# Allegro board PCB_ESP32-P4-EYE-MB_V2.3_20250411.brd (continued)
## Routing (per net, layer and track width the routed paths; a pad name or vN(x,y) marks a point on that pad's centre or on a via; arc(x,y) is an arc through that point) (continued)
C6_U0TXD: length 34.4
  TOP w0.127: U11.31 v1(33.58,30.9) ; R250.2 28.02,12.43 v1(27.97,12.38)
  BOTTOM w0.127: v1(27.97,12.38) 27.7,12.65 23.95,12.65 21.96,14.64 21.96,20.41 21.64,20.73 21.64,22.5 21.96,22.82 21.96,25.03 24.04,27.11 29.65,27.11 33.44,30.9 v1(33.58,30.9) 33.58,31.4 TP47.1
CAM_3V3: length 28.9
  TOP w0.3: J24.23 39.25,33.74 39,33.99 38.75,33.73 J24.24
  TOP w0.381: v1(38.21,34.45) C47.1 39,34.17 39,33.99
  L5_POWER w0.381: v1(54.19,26.29) v1(56.78,26.29)
  BOTTOM w0.381: U16.5 C141.1 TP51.1 57.61,26.29 v1(56.78,26.29) ; v1(54.19,26.29) 52.11,26.29 47.55,30.85 42.43,30.85 38.83,34.45 v1(38.21,34.45)
CAM_CN: length 2.1
  TOP w0.089: R25.1 46.87,34.76 46.87,34.5 C164.1 46.87,34.16 46.87,33.98 46.75,33.86 J24.8
CAM_CP: length 2.1
  TOP w0.089: J24.7 47.25,33.86 47.13,33.98 47.13,34.15 47.3,34.33 47.13,34.5 47.13,34.77 R24.1
CAM_DN: length 2.1
  TOP w0.089: J24.19 41.25,33.77 41.13,33.89 41.13,34.17 C165.1 41.11,34.5 41.11,34.76 R27.1
CAM_DP: length 2.1
  TOP w0.089: R26.1 40.85,34.76 40.85,34.5 C166.1 40.87,34.14 40.87,33.88 40.75,33.77 J24.20
CAM_I2C_SCL: length 6.5
  TOP w0.127: v1(50.32,30.72) 49.25,31.79 J24.3
  BOTTOM w0.127: R303.1 53.95,30.72 v1(50.32,30.72)
CAM_I2C_SDA: length 7.2
  TOP w0.127: v1(50.23,31.42) 49.75,31.9 J24.2
  BOTTOM w0.127: R302.1 50.34,30.06 49.92,30.48 49.92,31.11 v1(50.23,31.42)
CAM_MCLK: length 1.6
  TOP w0.127: J24.5 48.25,34.11 R304.2
CAM_RESET: length 23.2
  TOP w0.127: v1(39.57,32.16) 39.75,32.33 J24.22 39.75,34.07 R67.2 ; v1(29.82,17.07) 29.87,17.02 U4.55
  L5_POWER w0.127: v1(29.82,17.07) 31.47,18.72 33.46,18.72 39.45,24.7 39.45,32.03 v1(39.57,32.16)
CNN_GPIO6: length 20.7
  TOP w0.127: U4.6 48.55,10.72 53.42,15.58 53.42,18.01 53.73,18.33 53.73,19.2 54.3,19.77 J22.9
CNN_GPIO7: length 26.6
  TOP w0.127: J22.8 58.73,22.31 57.44,21.02 54.18,21.02 53.43,20.27 53.43,18.5 53.11,18.19 53.11,15.74 48.44,11.07 U4.7
CNN_GPIO8: length 22.5
  TOP w0.127: U4.8 40.67,11.42 40.74,11.34 48.23,11.34 52.29,15.39 52.29,17.82 53.1,18.63 53.1,21.11 54.3,22.31 J22.7
CNN_GPIO10: length 24.4
  TOP w0.127: U4.11 40.58,12.47 40.75,12.29 41.71,12.29 42.08,11.93 47.88,11.93 50.86,14.91 50.86,21.21 53.86,24.21 53.86,24.4 54.31,24.85 J22.5
CNN_GPIO34: length 61.6
  TOP w0.127: U4.65 29.61,13.52 29.34,13.79 28.18,13.79 v1(28.07,13.68) ; v1(41.5,11.9) 41.77,11.63 48.06,11.63 51.46,15.04 51.46,21.29 53.9,23.72 57.59,23.72 58.72,24.85 J22.6
  L3_SIGNAL w0.127: v1(41.5,11.9) 42.99,11.9 44.11,13.02 44.11,13.39 43.85,13.64 43.85,19.98 42.67,21.16 39.71,21.16 37.15,18.59 34.73,18.59 34.16,18.02 32.26,18.02 31.95,17.72 31.95,14.24 31.33,13.61 28.13,13.61 v1(28.07,13.68)
CNN_GPIO37: length 51.2
  TOP w0.127: R259.2 26.43,11.67 23.94,9.18 23.94,1.31 24.38,0.86 32.42,0.86 32.6,0.69 48.72,0.69 54.19,6.16 56.88,6.16 57.79,7.07 J22.20
CNN_GPIO38: length 47.2
  TOP w0.127: J22.19 54.2,7.07 53.86,6.73 53.86,6.4 48.4,0.94 32.83,0.94 32.65,1.12 24.54,1.12 24.21,1.45 24.21,9.06 26.44,11.29 28.34,11.29 R118.2
CNN_GPIO50: length 35
  TOP w0.127: U4.93 35.84,7.55 34.9,6.62 34.9,2.97 36.39,1.49 47.79,1.49 53.53,7.23 53.53,7.82 54.06,8.36 57.49,8.36 58.75,9.61 J22.18
CNN_GPIO51: length 30.2
  TOP w0.127: J22.17 54.29,9.61 53.25,8.57 53.25,7.42 47.68,1.84 36.59,1.84 35.15,3.28 35.15,6.5 36.19,7.54 U4.94
CNN_GPIO52: length 35.8
  TOP w0.127: J22.16 58.76,12.15 57.54,10.93 53.85,10.93 52.95,10.03 52.95,7.57 47.57,2.2 36.74,2.2 35.41,3.53 35.41,6.39 36.54,7.52 U4.95
CNN_GPIO53: length 31
  TOP w0.127: J22.15 54.31,12.15 52.64,10.48 52.64,7.73 47.49,2.58 36.83,2.58 35.66,3.75 35.66,6.27 37.24,7.85 U4.97
CNN_GPIO54: length 32.7
  TOP w0.127: J22.13 54.3,14.69 52.34,12.73 52.34,7.9 47.35,2.91 36.97,2.91 35.92,3.96 35.92,6.16 37.59,7.83 U4.98
CSI_CLKN: length 25.4
  TOP w0.089: R283.2 33.04,20.3 33.04,20.4 v1(32.88,20.56) ; v1(46.7,35.93) 46.86,35.77 46.86,35.64 R25.2
  L3_SIGNAL w0.089: v1(32.88,20.56) 33.04,20.72 33.04,20.97 33.48,21.4 35.5,21.4 36.21,22.11 36.21,26.12 39.35,29.26 42.42,29.26 46.87,33.72 46.87,35.76 v1(46.7,35.93)
CSI_CLKN_A: length 1.6
  TOP w0.089: R283.1 33.03,19.41 33.03,19.18 33.43,18.78 33.43,18.65 33.39,18.61 U4.45
CSI_CLKP: length 25.4
  TOP w0.089: v1(33.46,20.56) 33.3,20.4 33.3,20.27 R284.2 ; v1(47.29,35.93) 47.13,35.76 47.13,35.64 R24.2
  L3_SIGNAL w0.089: v1(33.46,20.56) 33.3,20.72 33.3,20.86 33.58,21.14 35.6,21.14 36.46,22 36.46,26.01 39.46,29 42.52,29 47.13,33.61 47.13,35.77 v1(47.29,35.93)
CSI_CLKP_A: length 1.6
  TOP w0.089: R284.1 33.29,19.41 33.29,19.29 33.69,18.88 33.69,18.66 33.74,18.61 U4.44
CSI_DATA0N: length 25.1
  TOP w0.089: R286.2 35.01,20.29 35.01,22.15 v1(35.17,22.31) ; v1(41.29,35.97) 41.13,35.81 41.13,35.64 R27.2
  L3_SIGNAL w0.089: v1(41.29,35.97) 41.12,35.81 41.12,32.11 39.32,30.3 39.01,30.3 38.56,29.85 38.2,29.85 37.65,30.41 37.5,30.41 37.4,30.3 37.4,30.15 37.95,29.6 37.95,29.24 37.7,28.98 37.34,28.98 36.78,29.54 36.63,29.54 36.53,29.44 36.53,29.29 37.09,28.73 37.09,28.37 36.83,28.12 36.47,28.12 35.92,28.67 35.77,28.67 35.66,28.57 35.66,28.42 36.22,27.87 36.22,27.51 35.28,26.57 35.28,23.18 35.01,22.9 35.01,22.48 v1(35.17,22.31)
CSI_DATA0N_A: length 1.8
  TOP w0.089: R286.1 35.01,19.42 35.01,19.18 34.73,18.9 34.53,18.9 34.39,18.76 34.39,18.65 34.44,18.61 U4.42
CSI_DATA0P: length 25.1
  TOP w0.089: v1(40.7,35.97) 40.86,35.81 40.86,35.66 R26.2 ; R285.2 34.75,20.29 34.75,22.15 v1(34.59,22.31)
  L3_SIGNAL w0.089: v1(40.7,35.97) 40.87,35.81 40.87,32.21 39.21,30.56 38.91,30.56 38.46,30.11 38.31,30.11 37.75,30.66 37.39,30.66 37.14,30.41 37.14,30.05 37.7,29.49 37.7,29.35 37.59,29.24 37.44,29.24 36.89,29.8 36.53,29.8 36.27,29.54 36.27,29.18 36.83,28.63 36.83,28.48 36.72,28.38 36.58,28.38 36.02,28.93 35.66,28.93 35.41,28.68 35.41,28.32 35.96,27.76 35.96,27.61 35.02,26.67 35.02,23.28 34.75,23.01 34.75,22.48 v1(34.59,22.31)
CSI_DATA0P_A: length 1.8
  TOP w0.089: R285.1 34.75,19.41 34.75,19.29 34.63,19.16 34.42,19.16 34.13,18.87 34.13,18.65 34.09,18.61 U4.43
CSI_REXT: length 1.5
  TOP w0.18: U4.48 32.34,19.19 R203.1
DSI_REXT: length 0.9
  TOP w0.18: R202.1 37.24,19.06 U4.34
EN_DCDC: length 5.3
  TOP w0.127: v1(28.32,5.91) 28.32,6.88 29.41,7.98 30.7,7.98 30.94,8.22 U4.79
  BOTTOM w0.127: v1(28.32,5.91) 28.32,5.78 28.32,5.78 U1.1
ENCODER_A: length 46.4
  TOP w0.127: v1(34.79,7.44) U4.90 ; R292.1 23.01,10.38 v1(22.17,9.53) 21.15,9.53 20.18,10.5 20.18,13.7 19.56,14.33 18.26,14.33 16.89,15.7 16.89,20.55 15.98,21.46 10.68,21.46 7.94,24.21 7.94,24.81 SW6.1
  L3_SIGNAL w0.127: v1(34.79,7.44) 34.7,7.53 33.93,7.53 32.16,5.75 29.24,5.75 28.65,6.34 24.46,6.34 23.94,6.86 23.94,7.94 22.35,9.53 v1(22.17,9.53)
ENCODER_B: length 36.9
  TOP w0.127: SW6.4 15.62,25.15 18.05,22.72 18.05,16.76 21.76,13.06 22.23,13.06 R293.1 21.35,11.88 v1(21.35,10.35) ; v1(34.4,7.07) 34.37,7.11 34.37,7.86 34.44,7.93 U4.89
  L3_SIGNAL w0.127: v1(21.35,10.35) 21.35,9.66 21.91,9.11 22.36,9.11 23.6,7.87 23.6,6.34 24.51,5.42 32.26,5.42 32.75,5.92 33.45,5.92 34.4,6.86 v1(34.4,7.07)
ENCODER_SW: length 47.7
  TOP w0.127: v1(40.97,8.81) 40.97,9 40.66,9.32 U4.2 ; SW6.2 10.12,23.81 R295.1 10.93,23.81 12.45,22.29 16.24,22.29 17.49,21.04 17.49,16.14 v1(18.62,15.01)
  L3_SIGNAL w0.127: v1(18.62,15.01) 18.48,14.86 18.48,13.36 19.18,12.66 19.94,12.66 21.44,11.16 21.44,10.87 24.27,8.04 24.27,6.95 24.63,6.59 28.77,6.59 29.31,6.05 32.07,6.05 33.86,7.84 38.48,7.84 39.14,7.18 39.74,7.18 40.14,7.58 40.14,8.46 40.5,8.81 v1(40.97,8.81)
ESP_3V3: length 187.8
  TOP w0.18: 38.62,8.78 38.64,8.76 U4.101 ; U4.51 31.29,17.86 ; 39.75,15.97 U4.21 ; U4.62 30.8,14.57 v1(31.04,14.33) ; U4.75 v1(30.99,10.02) ; v1(31,9.32) U4.77 ; 38.99,8.79 U4.102 ; v1(39.59,11.77) U4.9 ; 36.89,8.78 U4.96
  TOP w0.2: v1(31.29,23.5) 31.1,23.69 R135.2 ; R4.2 R3.1 26.53,12.43 v1(26.02,11.93)
  TOP w0.254: v1(36.89,9.08) 36.89,8.78 ; v1(39.13,9.09) 38.99,8.95 38.99,8.79 ; C110.1 21.07,32.45 R134.2 ; 38.62,8.78 38.62,8.9 v1(38.46,9.07) ; v1(10.74,23.03) 10.46,23.31 R295.2 ; 31.29,17.86 31.29,17.72 v1(31.37,17.64)
  TOP w0.381: v1(39.45,15.97) 39.75,15.97
  TOP w0.635: C109.1 C110.1 21.17,32.46 22.46,32.46 U11.3
  L3_SIGNAL w0.254: v1(22.03,7.33) 21.16,6.45 v1(21.16,1.89)
  L5_POWER w0.2: 20.22,11.98 20.16,11.92 v1(19.47,11.92) ; v1(26.02,11.93) 26.02,11.76 25.49,11.23 ; 51.67,20.5 51.71,20.46 52.27,20.46 v1(52.4,20.33) ; 19.65,25.36 13.08,25.36 v1(10.74,23.03) ; v1(20.08,18.87) 20.33,18.87
  L5_POWER w0.508: 52.13,20.97 52.4,20.7 v1(52.4,20.33) ; v1(36.61,20.56) 38.07,19.11 38.07,15.92
  L5_POWER w0.762: 21.22,2.18 21.22,6.63 20.22,7.63 20.22,11.98 20.74,12.5 20.74,17.49 20.33,17.89 20.33,23.9 v1(19.81,24.42) 19.65,24.59 v1(19.65,32.07) ; 40.16,10.9 46.35,10.9 50.11,14.66 50.11,18.95 52.13,20.97 63.18,20.97 67.13,24.92 67.13,31.41 66.93,31.61
  L5_POWER w1.2: v1(21.16,1.89) 21.31,1.74 22.21,1.74 23.65,3.17 23.65,9.39 25.49,11.23 28.17,11.23 29.58,12.64 29.58,12.92 30.58,13.92 31.29,13.92
  BOTTOM w0.2: R263.2 19.96,18.76 v1(20.08,18.87) ; 33.77,24.57 33.77,25.43 R133.1 34.25,25.45 34.54,25.74 R132.1 R131.1 R130.1 R129.1 R128.1 ; 33.77,24.57 34.34,24 34.92,24 36.2,22.73 36.2,21.4 Q8.2 ; 33.77,24.57 32.11,24.57 31.29,23.76 v1(31.29,23.5) ; R262.2 19.88,24.36 v1(19.81,24.42) ; v1(52.4,20.33) 52.69,20.04 53.12,20.04 R306.1 ; v1(36.61,20.56) 36.61,20.41 R309.2 ; R2.2 39.89,9.59 C82.1 ; C174.1 64.39,34.08 R230.2 ; v1(19.47,11.92) R264.2
  BOTTOM w0.254: R146.1 C121.1 21.79,7.33 v1(22.03,7.33)
  BOTTOM w0.381: C90.1 36.89,9.59 v1(36.89,9.08) ; v1(31,9.32) 31.14,9.18 C96.1 C95.1 ; C88.1 39.35,16.06 v1(39.45,15.97) ; C87.1 39.31,11.49 v1(39.59,11.77) 39.87,11.49 C83.1 ; C85.1 38.07,9.45 v1(38.46,9.07) ; C82.1 C84.1 39.13,9.42 v1(39.13,9.09) ; TP53.1 27.47,32.42 19.82,32.42 v1(19.65,32.6) ; v1(30.99,10.02) 30.98,10.02 30.78,10.21 C103.1 ; v1(31.04,14.33) 31.05,14.31 C97.1 ; v1(52.4,20.33) 52.45,20.39 Q2.2 ; v1(31.14,14.86) 31.29,14.86 31.77,15.34 C98.1 C99.1 C100.1 31.84,17.17 v1(31.37,17.64)
  BOTTOM w0.508: v1(36.61,20.56) 36.12,21.05 Q8.2
  BOTTOM w0.635: TP49.1 21.58,2.64 22.59,3.66 22.59,5.72 24.69,7.82 C6.1 26.19,7.82 U1.4
  BOTTOM w0.762: Q10.2 63.08,33.14 63.58,32.63 C174.1 C178.1 v1(67.01,32.63)
  BOTTOM w1.2: 19.95,1.62 L5.2
  vias: v1(20.59,1.9) v1(20.61,1.34) v1(21.16,1.33) v1(67.01,32.06)
ESP_EN: length 49.1
  TOP w0.127: v1(19.2,13.64) 17.4,13.64 10.15,20.89 4.41,20.89 2.63,22.67 2.63,23 1.05,24.58 SW1.3 ; U4.103 39.34,7.93 v1(39.42,7.85)
  L3_SIGNAL w0.127: v1(39.42,7.85) 38.89,8.38 32.85,8.38 31.33,6.86 29.69,6.86 29.16,7.39 25.68,7.39 22.05,11.02 22.05,11.62 20.03,13.64 v1(19.2,13.64)
  BOTTOM w0.127: R2.1 39.51,7.85 v1(39.42,7.85) 39.42,7.85 C2.2
ESP_I2C_SCL: length 42.8
  TOP w0.127: U4.14 41.17,13.52 v1(41.24,13.45) ; J22.12 58.03,17.23 v1(57.32,17.95)
  L3_SIGNAL w0.127: v1(57.33,28.94) 56.67,28.94 55.5,27.77 55.5,18.66 56.03,18.12 57.14,18.12 v1(57.32,17.95)
  BOTTOM w0.127: v1(41.24,13.45) 41.33,13.36 41.76,13.36 42.66,12.46 50.25,12.46 54.94,17.14 56.52,17.14 v1(57.32,17.95) 57.51,17.95 58.28,18.72 58.28,20.03 58.01,20.3 U13.12 ; v1(57.33,28.94) 56.91,28.94 55.14,30.71 R273.1 54.47,30.71 R303.2
ESP_I2C_SDA: length 39.6
  TOP w0.127: J22.10 57.93,19.77 57.44,19.28 v1(57.44,18.47) ; v1(41.66,13.78) 41.57,13.87 U4.15
  L3_SIGNAL w0.127: v1(56.83,28.54) 55.83,27.53 55.83,18.83 56.2,18.47 v1(57.44,18.47)
  BOTTOM w0.127: U13.2 57.39,18.52 v1(57.44,18.47) 57.25,18.47 56.27,17.49 54.7,17.49 49.93,12.71 42.77,12.71 41.71,13.78 v1(41.66,13.78) ; R302.2 54.47,30.06 R272.1 55.31,30.06 v1(56.83,28.54)
ESP_LDO_VO1: length 34.3
  TOP w0.18: v1(30.99,11.45) 30.96,11.42 U4.71 ; 38.64,18.79 U4.30
  TOP w0.2: v1(43.03,13.41) 42.75,13.69 42.75,13.86 R7.2
  TOP w0.254: 38.64,18.79 40.09,20.24 40.37,20.24 C25.1 C20.1 42.41,20.37 v1(42.55,20.23)
  TOP w0.381: U2.8 43.37,20.2 C5.1 42.68,20.37 v1(42.55,20.23)
  L3_SIGNAL w0.2: v1(42.55,20.23) 43.27,19.51 43.27,15.67 42.62,15.02 42.62,13.82 v1(43.03,13.41)
  L3_SIGNAL w0.381: v1(30.99,11.45) 33.04,11.45 34.57,12.98 34.57,14.88 35.89,16.21 36.84,16.21 41.02,20.38 42.39,20.38 v1(42.55,20.23)
  BOTTOM w0.254: C56.1 30.03,12.02 TP26.1
  BOTTOM w0.381: v1(30.99,11.45) 30.82,11.62 C56.1
ESP_LDO_VO2: length 11.5
  TOP w0.18: v1(30.98,15.72) 30.87,15.62 U4.59 ; v1(30.95,12.89) 30.88,12.82 U4.67 ; 29.88,10.93 30.02,11.07 U4.72
  TOP w0.254: 29.88,10.93 29.77,10.82 v1(29.71,10.82) 29.64,10.75 C50.1
  BOTTOM w0.254: v1(29.71,10.82) TP24.1 28.71,11.02 28.71,12.74 29.97,14 ; 30.11,14.14 30.11,14.12 30.24,14 ; 30.11,14.14 29.97,14 ; 30.11,14.14 30.11,15.3 C105.1 30.88,15.63 v1(30.98,15.72) ; 29.97,14 30.24,14 ; 30.24,14 30.84,13.39 C104.1 v1(30.95,12.89)
ESP_LDO_VO3: length 10.8
  TOP w0.18: U4.41 v1(34.79,17.69) ; v1(30.98,10.72) U4.73
  BOTTOM w0.254: v1(34.79,17.69) 34.57,17.48 C93.1 C92.1 C91.1 34.57,13.43 TP27.1 33.17,11.56 32.19,11.56 31.68,11.04 C55.1 31.56,10.85 31.1,10.85 v1(30.98,10.72)
ESP_LDO_VO4: length 56.3
  TOP w0.18: 30.05,10.37 U4.74 ; 33.04,7.94 U4.85
  TOP w0.2: v1(49.1,25.04) 49.1,25.18 ; 49.1,25.18 47.18,25.18 ; 49.1,25.18 50.75,25.18 v1(50.89,25.04) ; v1(38.27,25.01) v1(40.31,25.01) 40.48,25.18 47.18,25.18 ; R293.2 R292.2 23.45,13.41 v1(24.02,13.97) ; 47.18,25.18 v1(47.18,25.04)
  TOP w0.254: v1(29.73,10.24) 29.86,10.37 30.05,10.37 ; 33.04,7.94 33.04,7.57 32.98,7.52
  TOP w0.381: v1(29.73,10.24) 29.67,10.24 29.28,9.85 C51.1 ; v1(32.82,7.36) 32.98,7.52
  L3_SIGNAL w0.254: v1(24.02,13.97) 25.29,12.7 26.38,12.7 28.84,10.24 v1(29.73,10.24)
  L5_POWER w0.254: v1(38.27,25.01) 38.07,25.01 37.35,24.28 35.06,24.28 32.28,21.49 30.91,21.49 29.07,19.66 29.07,16.41 28.61,15.95 28.61,15.09 28.04,14.52 27.75,14.52 26.95,13.72 24.27,13.72 v1(24.02,13.97)
  L5_POWER w0.3: v1(32.82,7.36) 31.65,7.36 30.21,8.8 30.21,9.75 v1(29.73,10.24)
  BOTTOM w0.2: R17.1 47.25,25.11 v1(47.18,25.04) ; R231.1 49.06,25.08 v1(49.1,25.04) ; v1(40.31,25.01) 40.31,25.01 R232.1 ; R280.1 R233.1 38.45,25.26 38.27,25.07 v1(38.27,25.01) ; R234.1 v1(50.89,25.04)
  BOTTOM w0.381: v1(32.82,7.36) 32.82,7 C101.1 C102.1 32.51,5.71 TP25.1
ESP_VDD_HP: length 40.7
  TOP w0.18: 30.03,9.67 U4.76 ; U4.26 39.72,17.72 v1(39.54,17.54) ; 35.14,8.84 U4.91
  TOP w0.254: v1(29.29,1.98) 28.3,2.97 28.3,4.41 25.97,6.73 v1(25.97,9.65) ; v1(35.15,9.07) 35.14,9.05 35.14,8.84 ; v1(29.72,9.42) 29.97,9.67 30.03,9.67
  BOTTOM w0.254: R8.1 26.51,9.65 C7.1 v1(25.97,9.65)
  BOTTOM w0.381: v1(39.54,17.54) 39.16,17.92 C86.1 38.62,17.46 37.16,16 37.16,12.19 35.26,10.29 35.26,9.17 v1(35.15,9.07) ; 30.69,8.15 30.69,8.16 30.01,8.84 C107.1 29.81,9.33 v1(29.72,9.42)
  BOTTOM w0.508: v1(35.15,9.07) 35.08,9 C94.1 34.64,8.91 33.96,8.23 30.77,8.23 30.69,8.15
  BOTTOM w0.635: 30.69,8.15 C89.1 30.69,6.65 29.83,5.79 29.83,2.53 v1(29.29,1.98) C173.1 C8.1 27.85,1.98 L1.2
FB_DCDC: length 5.2
  TOP w0.18: 29.99,8.97 U4.78
  TOP w0.254: v1(28.83,8.88) 28.93,8.78 29.79,8.78 29.99,8.97
  BOTTOM w0.254: R9.1 28.32,8.79 U1.5 ; R9.1 R8.2 26.51,8.79 C7.2 ; R9.1 28.74,8.79 v1(28.83,8.88)
FLASH_CK: length 12.4
  TOP w0.127: U2.6 47.05,20.4 45.91,21.54 42.65,21.54 42.16,22.02 40.2,22.02 37.94,19.76 U4.32
FLASH_CS: length 10.1
  TOP w0.127: v1(44.54,13.97) 44.51,14 U2.1 ; R7.1 43.2,14.36 v1(43.15,14.4) 43.27,14.52 43.27,17.53 42.3,18.49 39.78,18.49 39.69,18.4 U4.27
  L5_POWER w0.127: v1(44.54,13.97) 44.11,14.4 v1(43.15,14.4)
FLASH_D: length 14.3
  TOP w0.127: U4.33 37.59,19.78 40.09,22.29 42.28,22.29 42.76,21.81 46.92,21.81 48.32,20.41 U2.5
FLASH_HD: length 10.4
  TOP w0.127: U2.7 45.78,20.83 45.43,21.18 39.72,21.18 38.23,19.69 38.23,18.75 38.29,18.68 U4.31
FLASH_Q: length 11.6
  TOP w0.127: U2.2 45.78,14.47 44.87,13.56 44.27,13.56 43.6,14.24 43.6,17.6 42.41,18.78 39.55,18.78 39.34,18.57 U4.28
FLASH_WP: length 11.7
  TOP w0.127: U4.29 38.99,18.59 39.44,19.04 42.56,19.04 43.89,17.7 43.89,15.7 44.17,15.42 46.53,15.42 47.05,14.9 U2.3
GPIO0: length 2.3
  TOP w0.127: R61.1 41.12,7.67 40.28,7.67 39.69,8.27 U4.104
GPIO1: length 1.9
  TOP w0.127: U4.1 40.45,8.97 40.58,8.84 40.58,8.22 40.77,8.02 R59.1
GPIO11: length 34.7
  TOP w0.127: R304.1 51.44,34.57 53.21,32.79 53.21,24.73 49.57,21.08 49.57,14.62 47.68,12.73 41.92,12.73 41.74,12.55 40.87,12.55 40.6,12.82 U4.12
GPIO21: length 1.1
  TOP w0.127: U4.23 40.58,16.67 40.67,16.75 41.03,16.75 R255.1
GPIO22: length 1.2
  TOP w0.127: U4.24 40.66,17.02 R23.1
GPIO24: length 2.2
  TOP w0.114: R104.1 29.19,18.36 30.22,18.36 30.41,18.55 30.81,18.55 30.94,18.43 U4.52
GPIO25: length 1.7
  TOP w0.114: R105.1 29.05,17.96 29.17,18.07 29.96,18.07 30.07,17.96 30.07,17.83 30.19,17.72 U4.53
GPIO27: length 1.9
  TOP w0.114: U4.56 29.61,16.67 29.27,17.01 R278.1
GPIO28: length 1.8
  TOP w0.114: U4.57 29.47,16.32 29.43,16.36 R277.1
GPIO29: length 3
  TOP w0.114: R276.1 28.77,15.81 28.92,15.97 U4.58
GPIO30: length 1.8
  TOP w0.114: R275.1 28.65,15.16 29.76,15.16 29.86,15.27 U4.60
GPIO31: length 3
  TOP w0.114: R274.1 27.53,14.81 29.83,14.81 29.94,14.92 U4.61
GPIO32: length 1.9
  TOP w0.114: U4.63 30,14.22 29.77,14.45 28.65,14.45 R279.1
GPIO35_BOOT: length 44.1
  TOP w0.127: SW2.3 1.05,32.04 2.11,33.1 13.35,33.1 18.87,27.57 18.87,18.81 19.63,18.05 20.89,18.05 25.49,13.45 25.49,13.27 C3.1 R4.1 26.44,13.15 26.78,13.5 27.69,13.5 27.9,13.28 28.24,13.28 28.49,13.53 28.93,13.53 29.22,13.24 R300.1 29.23,13.17 U4.66
GPIO36: length 3.3
  TOP w0.127: U4.68 29.25,12.47 R250.1 29.22,12.51 28.96,12.78 27.78,12.78 R3.2
GPIO37: length 2.5
  TOP w0.127: R259.1 28.42,12.05 29.86,12.05 29.92,12.12 U4.69
GPIO38: length 1.2
  TOP w0.127: R118.1 29.31,11.77 U4.70
GPIO39: length 2.6
  TOP w0.114: R122.1 29.66,6.74 30.54,7.62 30.82,7.62 31.29,8.09 U4.80
GPIO40: length 2.3
  TOP w0.114: R110.1 30.84,7.32 30.94,7.32 31.64,8.02 U4.81
GPIO41: length 2.1
  TOP w0.114: R108.1 31,6.83 31,6.99 31.99,7.97 U4.82
GPIO42: length 2
  TOP w0.114: U4.83 32.34,7.89 31.56,7.11 R107.1
GPIO43: length 1.9
  TOP w0.114: U4.84 32.69,7.82 32.19,7.33 R103.1
GPIO44: length 1.9
  TOP w0.114: R102.1 33.4,7.31 33.4,8.4 U4.86
LCD_BL: length 21.4
  TOP w0.127: v1(40.78,16.32) 40.78,16.32 U4.22
  BOTTOM w0.127: Q2.1 54.35,19.91 R79.1 R306.2 53.76,18.33 49.77,14.35 45.92,14.35 44.87,13.3 44.16,13.3 43.62,13.83 42.91,13.83 42.25,14.49 41.07,14.49 40.46,15.1 40.46,16 v1(40.78,16.32)
LCD_CS: length 11.8
  TOP w0.127: U4.19 41.1,15.27 v1(41.16,15.33) 41.26,15.43 41.26,15.73 R241.1
  BOTTOM w0.127: v1(41.16,15.33) 41.16,15.27 41.43,15 42.42,15 44.08,16.66 44.08,21.48 43.75,21.81 J5.8
LCD_DC: length 12.4
  TOP w0.127: v1(40.86,15.77) 40.7,15.62 U4.20
  BOTTOM w0.127: v1(40.86,15.77) 40.77,15.68 40.77,15.16 41.19,14.74 42.53,14.74 44.36,16.57 44.36,21.67 44.25,21.78 J5.7
LCD_RST: length 12
  TOP w0.127: U4.16 41.45,14.22 42.62,15.39 R238.1 42.36,16.32 v1(42.24,16.21)
  BOTTOM w0.127: v1(42.24,16.21) 42.43,16.21 43.23,17.01 43.23,20.93 42.25,21.91 J5.11
LCD_SCLK: length 11
  TOP w0.127: U4.18 41.31,14.92 41.69,15.3 v1(41.69,15.39)
  BOTTOM w0.127: J5.9 43.25,21.82 43.8,21.27 43.8,16.75 42.3,15.25 41.83,15.25 v1(41.69,15.39)
LCD_SDA: length 10.9
  TOP w0.127: U4.17 41.43,14.57 42.16,15.3 v1(42.16,15.67)
  BOTTOM w0.127: v1(42.16,15.67) 42.27,15.67 43.52,16.93 43.52,21.08 42.75,21.85 J5.10
LED_A: length 8.7
  BOTTOM w0.3: J5.3 46.25,22.32 46.44,22.12
  BOTTOM w0.381: 46.44,22.12 48.35,22.12 49.91,23.69 53.14,23.69 Q2.3
LED_CTRL: length 20
  TOP w0.127: v1(40.93,18.06) 40.81,17.94 40.81,17.6 40.57,17.37 U4.25 ; Q4.1 42.6,35.79 42.91,35.48 R73.1 42.91,34.57 v1(42.73,34.39)
  L5_POWER w0.127: v1(42.73,34.39) 42.73,34.29 41.58,33.13 41.58,26.8 41.29,26.5 41.29,25.03 40.93,24.67 v1(40.93,18.06)
LED_K: length 2.5
  BOTTOM w0.3: J5.2 46.75,23.83 46.85,23.93
  BOTTOM w0.381: R243.1 47.02,24.09 46.85,23.93
LPI2S_CLK: length 26.2
  TOP w0.127: v1(42.1,17.7) 41.85,17.7 R23.2 ; 47.6,40.38 47.37,40.38 46.88,39.88 46.88,38.57 v1(45.2,36.89)
  L5_POWER w0.127: v1(42.1,17.7) 42.1,18.8 43.14,19.84 43.14,21.27 43.59,21.72 43.59,23.65 42.99,24.24 42.99,26.12 42.82,26.29 42.82,28.3 42.98,28.45 42.98,31.64 45.2,33.86 v1(45.2,36.89)
LPI2S_DAT: length 30
  TOP w0.127: v1(45.61,36.53) 45.9,36.82 48.95,36.82 49.7,37.57 49.7,39.89 49.21,40.38 U9.4 ; v1(42.19,17.17) 41.95,17.17 R255.2
  L5_POWER w0.127: v1(45.61,36.53) 45.61,33.78 43.29,31.47 43.29,28.78 43.79,28.28 43.79,27.11 43.31,26.63 43.31,24.31 43.89,23.72 43.89,21.6 43.45,21.16 43.45,19.77 42.49,18.82 42.49,17.48 v1(42.19,17.17)
PWR_CTRL: length 37.9
  TOP w0.127: v1(62.98,24.5) 62.32,25.16 62.32,27.79 61.73,28.37 v1(60.31,28.37) ; U4.13 40.81,13.17 v1(41.01,12.97)
  BOTTOM w0.127: R310.2 60.31,27.83 v1(60.31,28.37) Q1.1 ; v1(41.01,12.97) 42.08,11.9 52.84,11.9 62.98,22.03 v1(62.98,24.5) U16.3
SD1_CLK: length 50.6
  TOP w0.114: R103.2 v1(32.19,2.59)
  L3_SIGNAL w0.132: v1(41.92,25.91) 42.09,25.74 42.62,25.74 42.76,25.88 42.76,26.1 42.91,26.25 43.13,26.25 43.29,26.1 43.29,25.88 43.42,25.74 43.85,25.74 45.77,23.82 45.99,23.82 46.17,24 46.39,24 46.54,23.84 46.54,23.62 46.37,23.45 46.37,23.23 50.2,19.39 50.2,8.37 43.83,1.99 33.3,1.99 32.7,2.59 v1(32.19,2.59)
  BOTTOM w0.114: v1(41.92,25.91) D6.2 42.64,25.91 43.01,26.28 43.01,27.24 J21.5
SD1_CMD: length 50.9
  TOP w0.114: R102.2 32.7,6.11 v1(32.7,2.02)
  L3_SIGNAL w0.132: v1(46.88,25.91) 46.88,26.66 47.08,26.86 47.42,26.86 47.6,26.68 47.6,24.17 47.75,24.01 48.64,24.01 48.82,23.84 48.82,23.55 48.67,23.39 48.26,23.39 48.11,23.24 48.11,23.02 48.26,22.86 48.5,22.86 48.63,22.73 48.63,21.59 50.65,19.57 50.65,8.2 44.04,1.6 33.12,1.6 v1(32.7,2.02)
  BOTTOM w0.114: R17.2 46.88,25.91 v1(46.88,25.91) D4.2 46.22,25.91 45.5,26.62 J21.3
SD1_D0: length 50.4
  TOP w0.114: R122.2 29.62,4.64 v1(30.82,3.43)
  L3_SIGNAL w0.132: v1(30.82,3.43) 32.41,3.43 33.45,2.39 43.59,2.39 49.78,8.59 49.78,19.19 43.64,25.34 41.25,25.34 v1(40.68,25.91)
  BOTTOM w0.114: R232.2 40.68,25.91 v1(40.68,25.91) D11.2 41.24,26.25 41.1,26.39 J21.7
SD1_D1: length 50.6
  TOP w0.114: R110.2 30.26,4.58 v1(30.82,4.03)
  L3_SIGNAL w0.132: v1(30.82,4.03) 31.17,4.03 31.27,3.92 31.69,3.92 31.79,4.03 32.36,4.03 33.6,2.78 43.36,2.78 49.34,8.76 49.34,19.05 44.93,23.46 42.39,23.46 41.69,24.16 40.56,24.16 v1(38.82,25.89)
  BOTTOM w0.114: J21.8 40,26.35 39.55,25.89 D10.2 v1(38.82,25.89) 38.82,25.9 R233.2
SD1_D2: length 50.8
  TOP w0.114: R108.2 31.24,5.91 v1(31.24,3)
  L3_SIGNAL w0.132: v1(50.52,25.91) 50.44,25.83 50.44,21.88 51.57,20.75 51.57,18.81 51.8,18.58 51.8,8.12 44.5,0.81 32.68,0.81 31.24,2.25 v1(31.24,3)
  BOTTOM w0.114: R234.2 50.52,25.91 v1(50.52,25.91) D8.2 49.8,25.91 49.14,26.57 48.3,26.57 47.7,27.17 J21.1
SD1_D3: length 50.7
  TOP w0.114: v1(31.66,2.67) 31.66,6.14 R107.2
  L3_SIGNAL w0.132: v1(31.66,2.67) 31.66,2.39 32.84,1.21 44.27,1.21 51.08,8.01 51.08,9.12 51.33,9.37 51.33,9.65 51.08,9.9 51.08,10.17 51.33,10.43 51.33,10.7 51.08,10.96 51.08,11.23 51.33,11.48 51.33,11.76 51.08,12.01 51.08,12.29 51.33,12.54 51.33,12.82 51.08,13.07 51.08,13.34 51.33,13.6 51.33,13.87 51.08,14.13 51.08,14.4 51.33,14.65 51.33,14.93 51.08,15.18 51.08,15.46 51.33,15.71 51.33,15.99 51.08,16.24 51.08,16.51 51.33,16.77 51.33,17.04 51.08,17.3 51.08,17.57 51.33,17.83 51.33,18.1 51.08,18.35 51.08,20.66 49.21,22.53 49.21,24.13 48.69,24.65 v1(48.69,25.91)
  BOTTOM w0.114: J21.2 46.6,27.23 47.92,25.91 D7.2 v1(48.69,25.91) 48.69,25.91 R231.2
SD1_VDD: length 11.6
  BOTTOM w0.381: C149.1 44.24,25.02 D3.2 44.24,26.02 44.4,26.18 J21.4 ; C149.1 44.37,24.66 43.94,24.23 41.11,24.23 40.51,23.63 Q8.3 ; C149.1 C148.1
SD2_CLK: length 15.7
  TOP w0.114: U11.25 v1(33.57,26.1) ; v1(27.69,16.32) 27.72,16.36 R277.2
  BOTTOM w0.114: R132.2 33.57,26.1 v1(33.57,26.1) 33.32,26.35 32.35,26.35 30.18,24.18 30.18,22.52 26.89,19.23 26.89,17.02 27.58,16.32 v1(27.69,16.32)
SD2_CMD: length 14.1
  TOP w0.114: v1(27.6,16.88) 27.72,17.01 R278.2 ; U11.24 33.2,25.78 v1(33.02,25.96)
  BOTTOM w0.114: R133.2 33.29,25.69 v1(33.02,25.96) 32.4,25.96 30.54,24.1 30.54,22.4 27.15,19.01 27.15,17.32 v1(27.6,16.88)
SD2_D0: length 16.1
  TOP w0.114: v1(27.09,16.26) 26.98,16.14 R276.2 ; U11.26 v1(33.58,26.9)
  BOTTOM w0.114: v1(27.09,16.26) 26.61,16.74 26.61,19.38 29.82,22.59 29.82,24.26 32.46,26.9 v1(33.58,26.9) 33.59,26.89 R131.2
SD2_D1: length 18.2
  TOP w0.114: U11.27 v1(33.59,27.7) ; R275.2 27.99,15.33 v1(27.74,15.33)
  BOTTOM w0.114: v1(27.74,15.33) 27.25,15.81 26.87,15.81 26.34,16.34 26.34,19.57 29.46,22.69 29.46,24.37 32.79,27.7 v1(33.59,27.7) 33.59,27.7 R130.2
SD2_D2: length 18.6
  TOP w0.114: R274.2 v1(26.98,15.33) ; U11.28 v1(33.59,28.5)
  BOTTOM w0.114: v1(26.98,15.33) 26.07,16.23 26.07,19.75 29.11,22.78 29.11,24.47 33.14,28.5 v1(33.59,28.5) 33.59,28.5 R129.2
SD2_D3: length 21.2
  TOP w0.114: U11.29 v1(33.59,29.3) ; v1(26.59,14.47) 28.08,14.47 R279.2
  BOTTOM w0.114: R128.2 33.59,29.3 v1(33.59,29.3) 33.45,29.3 28.77,24.61 28.77,22.9 25.81,19.94 25.81,15.25 v1(26.59,14.47)
SD_DET: length 51.8
  TOP w0.127: U4.87 33.74,4.2 v1(33.57,4.03)
  L3_SIGNAL w0.127: v1(48.76,9.73) 48.76,19 44.83,22.92 41.97,22.92 41.17,23.72 38.6,23.72 37.43,24.89 v1(37.43,25.9)
  L5_POWER w0.127: v1(33.57,4.03) 34.11,4.03 35.28,2.86 43.05,2.86 48.76,8.56 v1(48.76,9.73)
  BOTTOM w0.127: R280.2 v1(37.43,25.9) 37.42,25.9 D22.2 36.84,26.2 37.26,26.62 38.33,26.62 38.9,27.19 J21.9
SD_PWRN: length 59.6
  TOP w0.127: v1(38.02,22.12) 39.74,23.84 51.23,23.84 v1(51.9,24.51) ; v1(33.95,3.61) 34,3.66 34,7.92 34.09,8.01 U4.88
  L3_SIGNAL w0.127: v1(52.41,19.35) 53.09,20.03 53.09,23.33 v1(51.9,24.51)
  L5_POWER w0.127: v1(52.41,19.35) 52.29,19.23 52.29,10.16 44.56,2.44 35.12,2.44 v1(33.95,3.61)
  BOTTOM w0.127: v1(38.02,22.12) Q8.1 38.03,21.32 R308.2 R309.1
USB_DM: length 33.1
  TOP w0.114: U4.49 31.95,18.3 31.95,18.81 31.14,19.62 30.85,19.62 v1(30.71,19.76) ; v1(5.05,26.25) v1(5.05,25.26)
  L3_SIGNAL w0.127: v1(8.81,26.2) 8.94,26.07 14.95,26.07 21.4,19.62 30.57,19.62 v1(30.71,19.76)
  BOTTOM w0.114: J6.7 5.07,25.25 v1(5.05,25.26) ; 7.37,26.49 7.42,26.44 7.42,26.19 7.58,26.02 8.63,26.02 v1(8.81,26.2) ; 7.37,26.49 D20.2 ; 7.37,26.49 7.07,26.19 6.54,26.19 6.48,26.25 J6.9 v1(5.05,26.25)
USB_DP: length 35
  TOP w0.114: U4.50 31.66,18.29 31.66,18.69 31.02,19.33 30.88,19.33 v1(30.7,19.15)
  L3_SIGNAL w0.127: v1(8.81,25.59) 8.98,25.76 14.82,25.76 21.27,19.3 30.57,19.3 30.7,19.18 v1(30.7,19.15)
  BOTTOM w0.114: 7.37,25.27 7.1,25.54 7.1,25.78 6.98,25.9 6.67,25.9 6.52,25.75 J6.8 4.15,25.75 3.98,25.92 3.98,26.57 4.16,26.75 J6.10 ; 7.37,25.27 7.43,25.33 7.43,25.62 7.53,25.73 8.7,25.73 8.81,25.61 v1(8.81,25.59) ; 7.37,25.27 D21.2
USB_SJ_DN: length 29.2
  TOP w0.114: v1(28.05,18.49) 28.2,18.34 28.39,18.34 R104.2 ; v1(5.02,11.25) v1(5.02,10.25)
  L3_SIGNAL w0.127: v1(9.14,11.28) 9.14,11.28 9.26,11.15 9.4,11.15 9.55,11.15 11.2,12.8 13.76,12.8 19.06,18.1 25.43,18.1 25.68,18.35 27.92,18.35 v1(28.05,18.49)
  BOTTOM w0.114: J23.7 v1(5.02,10.25) ; v1(9.14,11.28) 8.99,11.13 7.77,11.13 7.3,11.6 D16.2 7.15,11.54 7.15,11.3 7.05,11.2 6.54,11.2 6.49,11.25 J23.9 v1(5.02,11.25)
USB_SJ_DP: length 31.7
  TOP w0.114: R105.2 28.55,17.93 28.44,18.05 28.22,18.05 v1(28.06,17.88)
  L3_SIGNAL w0.127: v1(9.14,10.69) 9.28,10.83 9.4,10.83 9.68,10.83 11.33,12.48 13.89,12.48 19.19,17.78 25.56,17.78 25.81,18.03 26.12,18.03 26.24,17.92 26.52,17.92 26.63,18.03 26.96,18.03 27.08,17.92 27.38,17.92 27.5,18.03 27.9,18.03 v1(28.06,17.88)
  BOTTOM w0.114: v1(9.14,10.69) 8.99,10.84 7.58,10.84 7.47,10.73 7.47,10.54 7.3,10.38 D17.2 7.12,10.46 7.12,10.79 7.01,10.91 6.68,10.91 6.52,10.75 J23.8 4.11,10.75 3.91,10.95 3.91,11.56 4.1,11.75 5.85,11.75 J23.10
VUSB: length 35.9
  L3_SIGNAL w1: v1(13.12,14.34) 12.5,14.96 12.5,23.3 13.51,24.31 13.89,24.31
  BOTTOM w0.381: R290.2 R291.2 8.93,2.86 SW7.3 8.93,7.9 10.3,9.27 10.3,10.77 11.24,11.71 ; U20.8 16.63,23.44 15.47,24.6 v1(14.17,24.6)
  BOTTOM w1: C169.2 11.27,16.4 10.58,15.71
  BOTTOM w1.2: Q6.2 6.33,17.24 7.43,16.14 10.15,16.14 10.58,15.71
  BOTTOM w1.8: D18.2 10.58,15.71
  vias: v1(13.67,14.34) v1(14.17,24.04)
VUSB1_IN: length 19.1
  TOP w1: 7.14,13.54 7.14,13.54 6.22,12.62 6.22,9.03 7.06,8.19
  L3_SIGNAL w0.254: v1(2.3,17.03) 5.46,17.03 8.24,14.25 v1(8.24,13.8)
  BOTTOM w0.254: D23.1 v1(2.3,17.03)
  BOTTOM w0.3: v1(6.75,8.51) 6.69,8.45 J23.3 ; v1(6.75,8.51) 7.06,8.2 v1(7.07,8.2) ; v1(6.75,8.51) 6.51,8.75 J23.4 ; v1(7.19,13.6) 7.15,13.55 J23.14 ; v1(6.79,13.25) J23.13
VUSB2_IN: length 20
  L3_SIGNAL w0.254: v1(2.3,18.33) 4.27,18.33 7.96,22.02 v1(7.96,22.77)
  L3_SIGNAL w1: 6.38,28.37 6.38,23.95 v1(6.69,23.63)
  BOTTOM w0.254: D23.2 v1(2.3,18.33)
  BOTTOM w0.3: 6.81,28.55 J6.14 ; 6.51,23.75 J6.4 ; 6.63,28.25 J6.13 ; 6.69,23.45 J6.3
  BOTTOM w1: D12.1 8.4,22.66 7.68,22.66
  vias: v1(6.74,28.44) v1(6.82,28.93) v1(7.04,23.23)
XTAL_N: length 1
  TOP w0.127: U4.99 37.94,7.6 R5.1
XTAL_P: length 1
  TOP w0.127: R1.1 38.29,7.67 U4.100
N16934509: length 4.4
  TOP w0.127: C1.1 39.37,4.06 Y1.1 38.66,4.78 38.66,6.8 R1.2
N16934523: length 2.4
  TOP w0.127: C4.1 37.67,5.67 Y1.3 37.83,5.91 R5.2
N18193822: length 1.4
  BOTTOM w0.635: U1.3 26.42,3.99 L1.1
N18255493: length 1.5
  BOTTOM w0.254: R142.2 6.56,24.75 J6.6
N18255499: length 1.4
  BOTTOM w0.254: R143.2 6.82,27.49 6.57,27.75 J6.12
N18262730: length 2.8
  BOTTOM w0.254: R148.1 R146.2 C121.2 20.66,7.6 U12.5
N18262777: length 1.6
  BOTTOM w0.2: R145.2 20.48,4.48 19.89,4.48 19.62,4.76 U12.1
N18262785: length 2
  BOTTOM w1: U12.3 17.72,3.82
  BOTTOM w1.2: L5.1 18.22,3.32 17.72,3.82
N18700058: length 2
  TOP w0.381: R72.1 44.13,40.8 D1.2
N18700064: length 1.8
  TOP w0.381: R72.2 44.28,39.24 43.55,38.51 Q4.3
N18877972: length 3
  TOP w0.254: 47.6,41.23 47.36,41.23 46.65,41.93 R246.2
N18902905: length 1.5
  BOTTOM w0.254: R268.2 6.84,9.4 6.49,9.75 J23.6
N18902911: length 1.4
  BOTTOM w0.254: J23.12 6.53,12.75 6.6,12.68 R269.2
N19010219: length 1.8
  BOTTOM w0.254: D23.3 4.97,17.68 R288.1 R289.1
N19010303: length 3.9
  BOTTOM w0.254: Q6.1 8.23,17.85 7.23,18.86 5.07,18.86 R289.2
N19013156: length 1.6
  BOTTOM w0.381: U20.2 15.36,15.13 R10.1
N19013226: length 2.8
  BOTTOM w0.381: D25.1 6.81,1.14 R290.1
N19013232: length 3.1
  BOTTOM w0.381: D5.1 5.34,4.17 7.25,2.26 R291.1
N19026853: length 3.8
  TOP w0.127: R61.2 42.49,7.36 R58.1 42.62,7.44 43.61,6.46 Y3.2 43.92,6.45 C19.1
N19026868: length 3.8
  TOP w0.127: R59.2 42.49,8.02 R58.2 42.64,7.94 43.6,8.91 Y3.1 43.92,8.91 C18.1
N19027177: length 3.7
  TOP w0.127: R298.2 23.7,23.06 R297.1 23.71,22.88 23.71,22.72 22.84,21.85 Y4.2 22.84,21.59 C170.1
N19027184: length 3.7
  TOP w0.127: C171.1 25.3,21.58 25.29,21.59 Y4.1 25.29,21.85 24.38,22.76 24.38,22.87 R297.2 24.34,23 R299.2
N19080261: length 2.3
  BOTTOM w0.254: Q9.1 12.9,9.8 11.55,8.46 R307.1
N19080264: length 5.7
  BOTTOM w0.254: SW7.2 11.43,7.59 R307.2
N19083043: length 7.4
  BOTTOM w0.2: R230.1 63.93,35.04 Q10.1 62.46,35.04 61.51,34.09 61.51,31.03 62.43,30.1 Q1.3

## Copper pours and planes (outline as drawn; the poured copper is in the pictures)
GND on TOP: 0.25,0.25 0.25,36.75 18,36.75 18.17,36.67 18.25,36.5 18.25,36.3 18.27,36.13 18.32,35.97 17.22,35.97 17.22,35.55 20.8,35.55 21.33,35.77 21.55,36.3 21.55,36.5 21.63,36.67 21.8,36.75 35.25,36.75 35.25,38.34 36.44,42.75 52.56,42.75 53.75,38.34 53.75,36.75 67.95,36.75 67.95,32.35 68.75,32.35 68.75,5.85 57.35,5.85 57.35,0.25 ; 6 cut-outs
GND on BOTTOM: 0.25,0.25 0.25,36.75 18,36.75 18.17,36.67 18.25,36.5 18.25,36.31 17.37,36.31 17.37,35.55 20.8,35.55 21.33,35.77 21.55,36.3 21.55,36.5 21.63,36.67 21.8,36.75 35.25,36.75 35.25,38.34 36.44,42.75 52.56,42.75 53.75,38.34 53.75,36.75 67.95,36.75 67.95,32.35 68.75,32.35 68.75,5.85 57.35,5.85 57.35,0.25 ; 3 cut-outs
GND on L2_GND1: 0.25,0.25 0.25,36.75 18,36.75 18.17,36.67 18.25,36.5 18.25,36.39 17.44,36.39 17.44,35.55 20.8,35.55 21.33,35.76 21.55,36.28 22.39,36.28 22.39,36.39 21.55,36.39 21.55,36.5 21.63,36.67 21.8,36.75 35.25,36.75 35.25,38.34 36.44,42.75 52.56,42.75 53.75,38.34 53.75,36.75 67.95,36.75 67.95,32.35 68.75,32.35 68.75,5.85 57.35,5.85 57.35,0.25
GND on L3_SIGNAL: 0.25,0.25 0.25,36.75 18,36.75 18.17,36.67 18.25,36.5 18.25,36.33 17.26,36.33 17.26,35.55 20.8,35.55 21.33,35.77 21.55,36.3 21.55,36.5 21.63,36.67 21.8,36.75 35.25,36.75 35.25,38.34 36.44,42.75 52.56,42.75 53.75,38.34 53.75,36.75 67.95,36.75 67.95,32.35 68.75,32.35 68.75,5.85 57.35,5.85 57.35,0.25
GND on L4_GND2: 0.25,0.25 0.25,36.75 18,36.75 18.17,36.67 18.25,36.5 18.25,36.3 18.25,36.21 18.27,36.12 17.48,36.12 17.48,35.55 20.8,35.55 21.26,35.71 21.53,36.12 21.55,36.21 21.55,36.3 21.55,36.5 21.63,36.67 21.8,36.75 35.25,36.75 35.25,38.34 36.44,42.75 52.56,42.75 53.75,38.34 53.75,36.75 67.95,36.75 67.95,32.35 68.75,32.35 68.75,5.85 57.35,5.85 57.35,0.25
GND on L5_POWER: 0.25,0.25 0.25,36.75 18,36.75 18.17,36.67 18.25,36.5 18.25,36.3 18.25,36.25 17.32,36.25 17.32,35.55 20.8,35.55 21.31,35.75 21.55,36.25 21.55,36.3 21.55,36.5 21.63,36.67 21.8,36.75 35.25,36.75 35.25,38.34 36.44,42.75 52.56,42.75 53.75,38.34 53.75,36.75 67.95,36.75 67.95,32.35 68.75,32.35 68.75,5.85 57.35,5.85 57.35,0.25 ; 1 cut-out
VBAT on BOTTOM (solid shape): 13.19,22.89 13.19,21.13 13.11,21.04 11.06,21.04 10.77,21.34 10.77,22.13 10.9,22.26 11.79,22.26 12.48,22.96 13.13,22.96
VCC_5V on TOP (solid shape): 15.94,10.66 15.94,10.02 15.7,9.78 12.25,9.78 11.96,10.07 11.96,10.52 12.43,10.99 15.61,10.99
VCC_5V on BOTTOM (solid shape): 12.74,10.73 12.74,10.44 11.91,9.6 11.06,9.6 11.02,9.64 11.02,10.54 11.33,10.86 12.62,10.86
VCC_5V on BOTTOM (solid shape): 18.55,11.42 18.55,7.52 18,6.96 17.27,6.96 16.9,7.33 16.9,9.28 16.28,9.91 14.97,9.91 14.82,10.06 14.82,11.09 15.18,11.44 18.53,11.44
ESP_3V3 on L5_POWER (solid shape): 67.35,32.71 67.35,31.74 67.51,31.57 67.51,31.32 67.36,31.17 66.8,31.17 66.52,31.45 66.52,32.69 66.71,32.88 67.18,32.88
ESP_3V3 on TOP: 19.55,32.83 20.46,32.83 20.52,32.77 20.52,32.25 20.13,31.85 19.53,31.85 19.42,31.97 19.42,32.7
ESP_3V3 on BOTTOM: 19.38,1.07 19.38,1.79 19.81,2.22 20.29,2.22 21.23,3.16 21.67,3.16 21.97,2.86 21.97,1.37 21.45,0.85 19.6,0.85
ESP_3V3 on L5_POWER: 20.92,2.57 21.54,2.57 21.96,2.15 21.96,1.51 21.56,1.12 20.49,1.12 20.36,1.24 20.36,2.01
ESP_3V3 on L5_POWER: 38.77,8.08 31.89,8.08 30.77,9.19 30.77,13.07 30.73,13.11 30.29,13.11 30.29,14.4 32.13,16.24 39.52,16.24 40.31,15.46 40.31,11.52 41.24,10.59 41.24,10.54
VUSB on BOTTOM (solid shape): 13.18,17.59 13.18,15.84 13.13,15.79 11.89,15.79 11.73,15.63 10.92,15.63 10.25,16.31 10.25,16.68 10.49,16.92 11.79,16.92 12.51,17.64 13.13,17.64
VUSB on BOTTOM (solid shape): 13.84,15.11 13.84,14.5 14.17,14.17 14.17,11.76 13.69,11.28 11.02,11.28 10.96,11.34 10.96,12.15 11.53,12.73 11.53,14.67 11.65,14.78 12.84,14.78 13.23,15.18 13.78,15.18
VUSB on L3_SIGNAL (solid shape): 13.91,14.45 13.91,14.2 13.54,13.83 12.92,13.83 12.69,14.06 12.69,14.48 12.88,14.67 13.69,14.67
VUSB on BOTTOM: 12.74,25.06 14.12,25.06 14.44,24.74 14.44,23.94 14.31,23.81 12.74,23.81 12.7,23.85 12.7,25.02
VUSB1_IN on BOTTOM (solid shape): 9.64,14.67 9.64,13.4 9.44,13.2 7.49,13.2 7.33,13.03 6.69,13.03 6.58,13.15 6.58,13.82 7.19,14.43 8.24,14.43 8.51,14.69 9.61,14.69
VUSB2_IN on BOTTOM (solid shape): 7.91,23.16 8.36,23.16 8.53,22.99 8.53,22.29 8.39,22.15 7.3,22.15 6.76,22.69 6.76,22.95 6.44,23.27 6.44,23.86 6.48,23.9 7.18,23.9
VUSB2_IN on L3_SIGNAL (solid shape): 7.26,23.77 7.26,23.11 7.15,23 6.62,23 6.13,23.48 6.13,23.9 6.36,24.13 6.91,24.13
VUSB2_IN on L3_SIGNAL (solid shape): 7.04,29.04 7.04,28.56 6.99,28.51 6.99,28.35 6.67,28.03 6.07,28.03 5.87,28.23 5.87,28.57 6.45,29.16 6.92,29.16

Small or netless copper shapes (teardrops, artwork), in the pictures only: 2 on TOP, 3 on BOTTOM, 1 on L3_SIGNAL, 1 on L5_POWER

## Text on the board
Ref Des/Silkscreen Bottom: USB HS | USB SJ | B2 | B3 | B1 | VO2 | VO1 | VO4 | C6: | VO3 | LCD | 3V3_P | CAM_AVDD | OFF | ON | 3V3 | GND | EN | BOOT | TX0 | RX0 | ESP32-P4-EYE-MB_V2.3 | HF
Ref Des/Silkscreen Top: BO | EN | BAT | CAMERA | - | +
User.7: FIGURE | SIZE | 0.254 | 0.5 | 0.6 | 1.0 | 1.6 | 1.4x0.6 | 1.7x0.6 | DRILL CHART: TOP to BOTTOM | ALL UNITS ARE IN MILLIMETERS | PLATED | NON-PLATED | QTY | 1095 | 2 | 4
